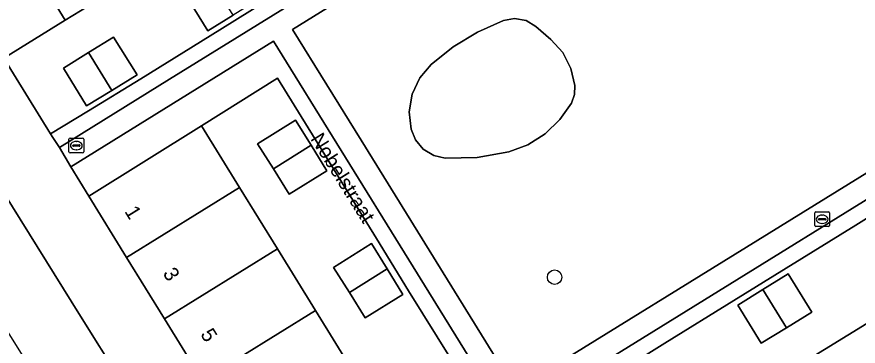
# Model space of a CAD drawing. Extents: x 159888 to 160761, y 384031 to 384750.
# Drawn here: x 160129.6 to 160186.6, y 384539.3 to 384561.6 of the extents above; entities that cross this region are included whole.
import ezdxf

# ---------------------------------------------------------------- set-up
doc = ezdxf.new("R2010")
doc.units = 0
for name, color, linetype in [('IMGEO_Boom', 7, 'Continuous'), ('IMGEO_Erf', 7, 'Continuous'), ('IMGEO_Groenvoorziening', 7, 'Continuous'), ('IMGEO_Kolk', 7, 'Continuous'), ('IMGEO_Openbare_ruimte_label', 7, 'Continuous'), ('IMGEO_Pand', 7, 'Continuous'), ('IMGEO_Pand_nummerreeks', 7, 'Continuous'), ('IMGEO_Parkeervlak_open', 7, 'Continuous'), ('IMGEO_Terreindeel_onvherhard', 7, 'Continuous'), ('IMGEO_Voetpad_open', 7, 'Continuous')]:
    doc.layers.add(name, color=color, linetype=linetype)

msp = doc.modelspace()

# ---------------------------------------------------------------- linework, layer by layer
at = {"layer": 'IMGEO_Boom'}
msp.add_circle((160166.053, 384544.009), 0.489, dxfattribs=at)
at = {"layer": 'IMGEO_Erf'}
for points in [[(160145.977, 384562.837), (160144.257, 384561.761), (160142.543, 384560.689), (160140.957, 384563.267), (160142.672, 384564.327), (160144.387, 384565.386)], [(160137.747, 384557.71), (160136.022, 384556.655), (160134.322, 384555.615), (160132.755, 384558.176), (160134.453, 384559.217), (160136.15, 384560.257)], [(160159.072, 384538.41), (160156.136, 384543.082), (160153.968, 384546.63), (160151.058, 384551.349), (160148.865, 384554.895), (160147.274, 384557.486), (160142.113, 384554.255), (160144.691, 384550.087), (160147.268, 384545.92), (160149.846, 384541.752), (160152.424, 384537.585), (160155.001, 384533.417), (160157.579, 384529.25), (160160.157, 384525.082), (160162.734, 384520.915), (160165.312, 384516.747), (160170.363, 384519.868), (160170.433, 384519.911), (160169.216, 384521.94), (160166.364, 384526.593), (160164.187, 384530.138), (160161.258, 384534.862)], [(160148.057, 384549.637), (160146.988, 384551.343), (160145.918, 384553.048), (160148.491, 384554.654), (160149.54, 384552.943), (160150.604, 384551.208)], [(160153.207, 384541.266), (160152.137, 384542.972), (160151.068, 384544.677), (160153.641, 384546.283), (160154.69, 384544.572), (160155.754, 384542.837)], [(160181.77, 384540.59), (160180.06, 384539.541), (160178.464, 384542.121), (160180.179, 384543.176), (160181.894, 384544.231), (160183.501, 384541.653)]]:
    msp.add_lwpolyline(points, close=True, dxfattribs=at)
for points in [[(160137.02, 384563.976), (160132.866, 384561.408), (160128.712, 384558.84), (160131.882, 384553.717), (160134.451, 384555.279), (160138.005, 384557.454), (160142.688, 384560.346), (160146.234, 384562.542)], [(160189.978, 384549.717), (160186.466, 384547.528), (160181.751, 384544.625), (160178.213, 384542.424), (160173.521, 384539.537), (160169.984, 384537.335), (160167.391, 384535.745), (160167.622, 384535.376), (160170.612, 384530.605), (160174.766, 384533.174), (160178.92, 384535.743), (160183.074, 384538.312), (160187.228, 384540.881)]]:
    msp.add_lwpolyline(points, dxfattribs=at)
at = {"layer": 'IMGEO_Groenvoorziening'}
msp.add_lwpolyline([(160189.322, 384578.257), (160186.066, 384583.561), (160185.149, 384585.056), (160180.644, 384582.188), (160181.266, 384581.183), (160148.281, 384560.789), (160152.94, 384553.3), (160163.406, 384536.375), (160200.868, 384559.503)], dxfattribs=at)
for points in [[(160179.214, 384581.669), (160178.648, 384582.593), (160177.945, 384582.154), (160176.59, 384581.308), (160175.649, 384580.721), (160170.932, 384577.817), (160167.402, 384575.62), (160162.717, 384572.729), (160159.181, 384570.545), (160154.504, 384567.651), (160150.964, 384565.459), (160146.234, 384562.542), (160142.688, 384560.346), (160138.005, 384557.454), (160134.451, 384555.279), (160131.882, 384553.717), (160132.027, 384553.482), (160132.473, 384552.799), (160139.949, 384557.419)], [(160167.391, 384535.745), (160169.984, 384537.335), (160173.521, 384539.537), (160178.213, 384542.424), (160181.751, 384544.625), (160186.466, 384547.528), (160189.978, 384549.717), (160194.673, 384552.612), (160198.249, 384554.781), (160202.905, 384557.7), (160206.438, 384559.861), (160211.144, 384562.778), (160214.703, 384564.976), (160217.276, 384566.598), (160217.169, 384566.771), (160216.709, 384567.521), (160214.269, 384566.02), (160201.679, 384558.218), (160164.199, 384535.04), (160170.426, 384524.933), (160172.677, 384521.294), (160175.354, 384522.92), (160170.612, 384530.605), (160167.622, 384535.376)], [(160167.429, 384556.987), (160167.398, 384556.377), (160167.187, 384555.805), (160166.412, 384554.681), (160165.406, 384553.716), (160164.227, 384552.975), (160162.949, 384552.494), (160160.802, 384552.108), (160158.621, 384552.079), (160157.857, 384552.252), (160157.149, 384552.677), (160156.614, 384553.304), (160156.316, 384554.03), (160156.195, 384555.201), (160156.396, 384556.407), (160156.914, 384557.513), (160157.679, 384558.409), (160159.184, 384559.601), (160160.832, 384560.601), (160162.585, 384561.386), (160163.341, 384561.525), (160164.123, 384561.385), (160164.785, 384560.992), (160165.805, 384560.11), (160166.602, 384559.224), (160167.161, 384558.149)], [(160142.113, 384554.255), (160147.274, 384557.486), (160148.865, 384554.895), (160151.058, 384551.349), (160153.968, 384546.63), (160156.136, 384543.082), (160159.072, 384538.41), (160161.258, 384534.862), (160164.187, 384530.138), (160166.364, 384526.593), (160169.216, 384521.94), (160170.433, 384519.911), (160170.652, 384520.047), (160171.445, 384520.533), (160169.806, 384523.173), (160156.159, 384545.179), (160147, 384559.992), (160133.251, 384551.488), (160134.463, 384549.497)]]:
    msp.add_lwpolyline(points, close=True, dxfattribs=at)
at = {"layer": 'IMGEO_Kolk'}
for p, q in [((160133.201, 384553.423), (160134.053, 384553.423)), ((160133.126, 384552.497), (160133.126, 384553.349)), ((160133.385, 384552.917), (160133.385, 384552.929)), ((160133.823, 384552.88), (160133.425, 384552.88)), ((160133.428, 384552.966), (160133.826, 384552.966)), ((160133.614, 384553.203), (160133.639, 384553.203)), ((160133.869, 384552.929), (160133.869, 384552.917)), ((160134.127, 384553.349), (160134.127, 384552.497)), ((160134.053, 384552.423), (160133.201, 384552.423)), ((160133.637, 384552.643), (160133.612, 384552.643)), ((160183.691, 384547.508), (160183.691, 384548.36)), ((160183.766, 384548.434), (160184.618, 384548.434)), ((160184.692, 384548.36), (160184.692, 384547.508)), ((160183.95, 384547.928), (160183.95, 384547.94)), ((160184.388, 384547.891), (160183.99, 384547.891)), ((160183.993, 384547.977), (160184.391, 384547.977)), ((160184.179, 384548.214), (160184.204, 384548.214)), ((160184.434, 384547.94), (160184.434, 384547.928)), ((160184.618, 384547.434), (160183.766, 384547.434)), ((160184.202, 384547.654), (160184.177, 384547.654))]:
    msp.add_line(p, q, dxfattribs=at)
for points in [[(160133.201, 384553.423), (160134.053, 384553.423)], [(160133.126, 384552.497), (160133.126, 384553.349)], [(160134.127, 384553.349), (160134.127, 384552.497)], [(160134.053, 384552.423), (160133.201, 384552.423)], [(160183.691, 384547.508), (160183.691, 384548.36)], [(160183.766, 384548.434), (160184.618, 384548.434)], [(160184.692, 384548.36), (160184.692, 384547.508)], [(160184.618, 384547.434), (160183.766, 384547.434)]]:
    msp.add_lwpolyline(points, dxfattribs=at)
for centre, radius, start, end in [((160133.203, 384553.347), 0.0765, 91.552, 178.448), ((160133.203, 384553.347), 0.0765, 91.552, 178.448), ((160134.051, 384553.347), 0.0765, 1.552, 88.448), ((160134.051, 384553.347), 0.0765, 1.552, 88.448), ((160133.425, 384552.926), 0.0403, 85.8775, 175.7526), ((160133.422, 384552.916), 0.0366, 178.938, 274.7102), ((160133.826, 384552.923), 0.043, 264.8664, 352.4533), ((160133.83, 384552.928), 0.0386, 1.7309, 96.639), ((160133.203, 384552.499), 0.0765, 181.552, 268.448), ((160133.203, 384552.499), 0.0765, 181.552, 268.448), ((160134.051, 384552.499), 0.0765, 271.552, 358.448), ((160134.051, 384552.499), 0.0765, 271.552, 358.448), ((160183.768, 384548.358), 0.0765, 91.552, 178.448), ((160183.768, 384548.358), 0.0765, 91.552, 178.448), ((160184.616, 384548.358), 0.0765, 1.552, 88.448), ((160184.616, 384548.358), 0.0765, 1.552, 88.448), ((160183.99, 384547.937), 0.0403, 85.8775, 175.7526), ((160183.987, 384547.927), 0.0366, 178.938, 274.7102), ((160184.391, 384547.934), 0.043, 264.8664, 352.4533), ((160184.395, 384547.939), 0.0386, 1.7309, 96.639), ((160183.768, 384547.51), 0.0765, 181.552, 268.448), ((160183.768, 384547.51), 0.0765, 181.552, 268.448), ((160184.616, 384547.51), 0.0765, 271.552, 358.448), ((160184.616, 384547.51), 0.0765, 271.552, 358.448)]:
    msp.add_arc(centre, radius, start, end, dxfattribs=at)
for centre, major_axis, ratio, start_param, end_param in [((160133.613, 384552.923), (-0.387, 0.002), 0.722429, 4.712389, 7.853982), ((160133.638, 384552.923), (-0.39, 0.002), 0.717154, 1.570796, 4.712389), ((160184.178, 384547.934), (-0.387, 0.002), 0.722429, 4.712389, 7.853982), ((160184.203, 384547.934), (-0.39, 0.002), 0.717154, 1.570796, 4.712389)]:
    msp.add_ellipse(centre, major_axis=major_axis, ratio=ratio, start_param=start_param, end_param=end_param, dxfattribs=at)
at = {"layer": 'IMGEO_Pand'}
for points in [[(160132.271, 384571.659), (160128.118, 384569.089), (160132.866, 384561.408), (160137.02, 384563.976)], [(160128.118, 384569.089), (160123.961, 384566.517), (160128.712, 384558.84), (160132.866, 384561.408)], [(160142.672, 384564.327), (160140.957, 384563.267), (160142.543, 384560.689), (160144.257, 384561.761)], [(160136.15, 384560.257), (160134.453, 384559.217), (160136.022, 384556.655), (160137.747, 384557.71)], [(160134.453, 384559.217), (160132.755, 384558.176), (160134.322, 384555.615), (160136.022, 384556.655)], [(160149.54, 384552.943), (160148.491, 384554.654), (160145.918, 384553.048), (160146.988, 384551.343)], [(160142.113, 384554.255), (160134.463, 384549.497), (160137.029, 384545.349), (160144.691, 384550.087)], [(160149.54, 384552.943), (160146.988, 384551.343), (160148.057, 384549.637), (160150.604, 384551.208)], [(160144.691, 384550.087), (160137.029, 384545.349), (160139.607, 384541.181), (160147.268, 384545.92)], [(160151.068, 384544.677), (160152.137, 384542.972), (160154.69, 384544.572), (160153.641, 384546.283)], [(160147.268, 384545.92), (160139.607, 384541.181), (160142.185, 384537.014), (160149.846, 384541.752)], [(160154.69, 384544.572), (160152.137, 384542.972), (160153.207, 384541.266), (160155.754, 384542.837)], [(160181.894, 384544.231), (160180.179, 384543.176), (160181.77, 384540.59), (160183.501, 384541.653)], [(160180.179, 384543.176), (160178.464, 384542.121), (160180.06, 384539.541), (160181.77, 384540.59)], [(160149.846, 384541.752), (160142.185, 384537.014), (160144.763, 384532.847), (160152.424, 384537.585)], [(160187.228, 384540.881), (160183.074, 384538.312), (160187.822, 384530.635), (160191.975, 384533.205)]]:
    msp.add_lwpolyline(points, close=True, dxfattribs=at)
at = {"layer": 'IMGEO_Parkeervlak_open'}
msp.add_lwpolyline([(160117.379, 384558.808), (160147.868, 384510.063), (160151.885, 384512.636), (160144.66, 384524.211), (160133.91, 384541.367), (160121.735, 384560.901), (160119.572, 384559.594), (160117.97, 384558.646)], dxfattribs=at)
at = {"layer": 'IMGEO_Terreindeel_onvherhard'}
msp.add_lwpolyline([(160167.429, 384556.987), (160167.161, 384558.149), (160166.602, 384559.224), (160165.805, 384560.11), (160164.785, 384560.992), (160164.123, 384561.385), (160163.341, 384561.525), (160162.585, 384561.386), (160160.832, 384560.601), (160159.184, 384559.601), (160157.679, 384558.409), (160156.914, 384557.513), (160156.396, 384556.407), (160156.195, 384555.201), (160156.316, 384554.03), (160156.614, 384553.304), (160157.149, 384552.677), (160157.857, 384552.252), (160158.621, 384552.079), (160160.802, 384552.108), (160162.949, 384552.494), (160164.227, 384552.975), (160165.406, 384553.716), (160166.412, 384554.681), (160167.187, 384555.805), (160167.398, 384556.377)], close=True, dxfattribs=at)
at = {"layer": 'IMGEO_Voetpad_open'}
for points in [[(160201.865, 384560.132), (160178.233, 384599.071), (160177.796, 384599.792), (160176.521, 384599.021), (160184.387, 384586.273), (160184.426, 384586.21), (160181.762, 384584.546), (160180.262, 384583.57), (160179.199, 384582.937), (160178.648, 384582.593), (160179.214, 384581.669), (160139.949, 384557.419), (160132.473, 384552.799), (160133.251, 384551.488), (160147, 384559.992), (160156.159, 384545.179), (160169.806, 384523.173), (160171.445, 384520.533), (160172.677, 384521.294), (160170.426, 384524.933), (160164.199, 384535.04), (160201.679, 384558.218)], [(160121.735, 384560.901), (160133.91, 384541.367), (160144.66, 384524.211)], [(160142.185, 384537.014), (160139.607, 384541.181), (160137.029, 384545.349), (160134.463, 384549.497), (160133.251, 384551.488), (160132.473, 384552.799), (160132.027, 384553.482), (160131.882, 384553.717), (160128.712, 384558.84)]]:
    msp.add_lwpolyline(points, dxfattribs=at)
msp.add_lwpolyline([(160196.17, 384567.098), (160200.122, 384560.709), (160200.868, 384559.503), (160163.406, 384536.375), (160152.94, 384553.3), (160148.281, 384560.789), (160181.266, 384581.183), (160180.644, 384582.188), (160185.149, 384585.056), (160186.066, 384583.561), (160189.322, 384578.257)], close=True, dxfattribs=at)

# ---------------------------------------------------------------- texts
at = {"layer": 'IMGEO_Openbare_ruimte_label'}
msp.add_text('Nobelstraat', height=1, rotation=302.0054, dxfattribs=at).set_placement((160149.464, 384553.381))
at = {"layer": 'IMGEO_Pand_nummerreeks'}
for s, p in [('1', (160136.863, 384548.468)), ('3', (160139.455, 384544.277)), ('5', (160142.007, 384540.151))]:
    msp.add_text(s, height=1, rotation=301.7417, dxfattribs=at).set_placement(p)

doc.saveas('drawing.dxf')
